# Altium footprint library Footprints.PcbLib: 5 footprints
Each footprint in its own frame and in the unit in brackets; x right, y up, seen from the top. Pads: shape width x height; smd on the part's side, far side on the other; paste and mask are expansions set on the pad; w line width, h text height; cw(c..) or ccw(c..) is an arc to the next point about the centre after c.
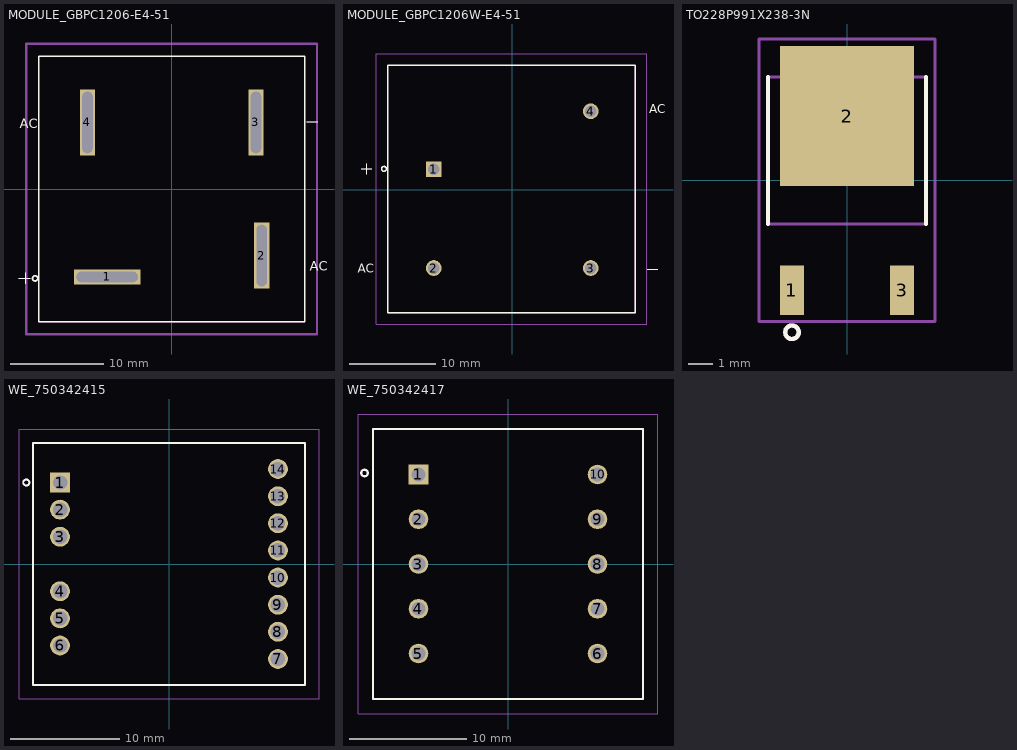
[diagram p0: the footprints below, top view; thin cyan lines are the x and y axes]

## MODULE_GBPC1206-E4-51 [mm]
height 7.87
pads (4):
  rect 7.104x1.614 hole 1.114 slot 6.604 at 0 deg mask+0: 1(-6.927,-9.45)
  rect 1.614x7.104 hole 1.114 slot 6.604 at 90 deg mask+0: 2(9.673,-7.15) 3(9.05,7.15) 4(-9.05,7.15)
Top Overlay:
  circle w0.178: c-14.679,-9.6 r0.279
  lines w0.127: -16.4,-9.6 -15.2,-9.6 ; -15.7,-10.2 -15.7,-9 ; 14.5,7.2 15.7,7.2
  lines w0.152: -14.275,-14.275 14.275,-14.275 14.275,14.275 -14.275,14.275 -14.275,-14.275
  text ".Designator" at -6,16 h1.02
  text "AC" at -16.3,6.5 h1.02
  text "AC" at 14.8,-8.8 h1.02
Mechanical 5:
  lines w0.127: -16.4,-9.6 -15.2,-9.6 ; -15.7,-10.2 -15.7,-9 ; 14.5,7.2 15.7,7.2 ; -14.275,-14.275 14.275,-14.275 14.275,14.275 -14.275,14.275 -14.275,-14.275
  text "PRELIMINARY" at -3,-3.8 h1.02
  text ".Designator" at -5,0 h1.02
Mechanical 15:
  lines w0.254: -15.609,-15.609 15.609,-15.609 15.609,15.609 -15.609,15.609 -15.609,-15.609
Drill Drawing:
  circle w0.178: c-14.679,-9.6 r0.279
Mechanical 17:
  text "LEAD LENGTH : 12.435MM" at -13.2,4.2 h1.27
3D body: height 7.87, standoff 0, extent -14.274,-14.274 14.274,14.274

## MODULE_GBPC1206W-E4-51 [mm]
height 7.87
pads (4):
  rect 1.824x1.824 hole 1.324 mask+0: 1(-9.05,2.35)
  round 1.824 hole 1.324 mask+0: 2(-9.05,-9.05) 3(9.05,-9.05) 4(9.05,9.05)
Top Overlay:
  circle w0.178: c-14.8,2.4 r0.279
  lines w0.127: -17.4,2.4 -16.2,2.4 ; -16.8,1.8 -16.8,3 ; 15.6,-9.2 16.8,-9.2
  lines w0.152: -14.35,-14.2 14.2,-14.2 14.2,14.35 -14.35,14.35 -14.35,-14.2
  text ".Designator" at -6,16 h1.02
  text "AC" at -17.8,-9.6 h1.02
  text "AC" at 15.8,8.8 h1.02
Mechanical 5:
  lines w0.127: -17.4,2.4 -16.2,2.4 ; -16.8,1.8 -16.8,3 ; 15.6,-9.2 16.8,-9.2 ; -14.35,-14.2 14.2,-14.2 14.2,14.35 -14.35,14.35 -14.35,-14.2
  text "PRELIMINARY" at -3,-3.8 h1.02
  text ".Designator" at -5,0 h1.02
Mechanical 15:
  lines w0.127: -15.684,-15.534 15.534,-15.534 15.534,15.684 -15.684,15.684 -15.684,-15.534
Drill Drawing:
  circle w0.178: c-14.8,2.4 r0.279
Mechanical 17:
  text "LEAD LENGTH : 23.93MM" at -13.2,4.2 h1.27
3D body: height 7.87, standoff 0, extent -14.349,-14.199 14.199,14.349

## TO228P991X238-3N [mm]
height 2.38
pads (3):
  rect 1x2.05 smd mask+0: 1(-2.285,-4.55) 3(2.285,-4.55)
  rect 5.55x5.8 smd mask+0: 2(0,2.65)
Top Overlay:
  circle w0.178: c-2.279,-6.3 r0.279
  lines w0.152: -3.27,-1.817 -3.27,4.277 ; 3.27,-1.817 3.27,4.277
  text ".Designator" at -5.5,6.6 h1.02
Mechanical 5:
  circle w0.178: c-2.279,-6.3 r0.279
  lines w0.127: -3.27,-1.817 3.27,-1.817 3.27,4.277 -3.27,4.277 -3.27,-1.817
  text ".Designator" at -5,-0.2 h1.02
  text "PRELIMINARY" at -2,-4.7 h1.02
Mechanical 15:
  lines w0.127: -3.65,-5.85 -3.65,5.85 3.65,5.85 3.65,-5.85 -3.65,-5.85
3D body: height 2.38, standoff 0, extent -3.269,-1.816 3.269,4.276

## WE_750342415 [mm] "TRANSFOERMER, TH"
height 16
pads (14):
  rect 1.82x1.82 / inner round 1.82 / far side rect 1.82x1.82 hole 1.32: 1(-10,7.48)
  round 1.82 hole 1.32: 2(-10,4.99) 3(-10,2.5) 4(-10,-2.5) 5(-10,-4.99) 6(-10,-7.48) 7(10,-8.715) 8(10,-6.225) 9(10,-3.735) 10(10,-1.245) 11(10,1.245) 12(10,3.735) 13(10,6.225) 14(10,8.715)
Top Overlay:
  circle w0.178: c-13.1,7.48 r0.279
  lines w0.178: -12.5,-11.1 12.5,-11.1 12.5,11.1 -12.5,11.1 -12.5,-11.1
  text ".Designator" at -1.524,12.954 h1.02
Bottom Overlay:
  lines w0.178: -12.5,-11.1 -12.5,-10.054 ; -12.5,-9.264 -12.5,-7.054 ; -12.5,-6.264 -12.5,-4.054 ; -12.5,-3.237 -12.5,-1.027 ; -12.5,-0.237 -12.5,1.973 ; -12.5,2.763 -12.5,4.973 ; -12.5,5.763 -12.5,7.973 ; -12.5,8.89 -12.5,11.1 -10.287,11.1 ; -10.894,-11.1 -8.627,-11.1 ; -9.5,11.1 -7.287,11.1 ; -7.894,-11.1 -5.627,-11.1 ; -6.5,11.1 -4.287,11.1 ; -4.894,-11.1 -2.627,-11.1 ; -3.5,11.1 -1.287,11.1 ; -1.894,-11.1 0.373,-11.1 ; -0.5,11.1 1.713,11.1 ; 1.106,-11.1 3.373,-11.1 ; 2.528,11.1 4.741,11.1 ; 4.106,-11.1 6.373,-11.1 ; 5.529,11.1 7.742,11.1 ; 7.106,-11.1 9.373,-11.1 ; 8.528,11.1 10.741,11.1 ; 10.233,-11.1 12.5,-11.1 12.5,-8.609 ; 12.5,-8.176 12.5,-5.685 ; 12.5,-5.176 12.5,-2.685 ; 12.5,-2.176 12.5,0.315 ; 12.5,0.824 12.5,3.315 ; 12.5,3.862 12.5,6.353 ; 12.5,6.862 12.5,9.353 ; 12.5,9.862 12.5,11.1
Mechanical 5:
  circle w0.127: c-13.1,7.48 r0.279
  lines w0.127: -12.5,-11.1 12.5,-11.1 12.5,11.1 -12.5,11.1 -12.5,-11.1
  text "PRELIMINARY" at -5.588,-7.112 h1.52
  text ".Designator" at -1.524,-0.508 h1.02
Mechanical 15:
  lines w0.05: -13.77,-12.37 -13.77,12.37 13.77,12.37 13.77,-12.37 -13.77,-12.37
Mechanical 17:
  text "LEAD LENGTH: 4:00 MM" at -10.668,9.652 h1
3D body: height 16, standoff 0, extent -12.5,-11.1 12.5,11.1

## WE_750342417 [mm] "TRANSFOERMER, TH"
height 17.53
pads (10):
  rect 1.67x1.67 / inner round 1.67 / far side rect 1.67x1.67 hole 1.17: 1(-7.62,7.62)
  round 1.67 hole 1.17: 2(-7.62,3.81) 3(-7.62,0) 4(-7.62,-3.81) 5(-7.62,-7.62) 6(7.62,-7.62) 7(7.62,-3.81) 8(7.62,0) 9(7.62,3.81) 10(7.62,7.62)
Top Layer:
  lines w0.178: 11.5,9 11.5,11.5
Top Overlay:
  circle w0.178: c-12.217,7.747 r0.279
  lines w0.178: -11.5,-11.5 -11.5,11.5 11.5,11.5 11.5,-11.5 -11.5,-11.5
  text ".Designator" at -1.524,12 h1.02
Bottom Overlay:
  lines w0.178: -11.5,-9.599 -11.5,-11.5 -9,-11.5 ; -11.5,-9.099 -11.5,-6.599 ; -11.5,-6.099 -11.5,-3.599 ; -11.5,-3.127 -11.5,-0.627 ; -11.5,-0.127 -11.5,2.373 ; -11.5,2.873 -11.5,5.373 ; -11.5,5.873 -11.5,8.373 ; -11.5,9 -11.5,11.5 -9,11.5 ; -8.5,-11.5 -6,-11.5 ; -8.5,11.5 -6,11.5 ; -5.5,-11.5 -3,-11.5 ; -5.5,11.5 -3,11.5 ; -2.5,-11.5 0,-11.5 ; -2.5,11.5 0,11.5 ; 0.5,-11.5 3,-11.5 ; 0.5,11.5 3,11.5 ; 3.5,-11.5 6,-11.5 ; 3.5,11.5 6,11.5 ; 6.5,-11.5 9,-11.5 ; 6.5,11.5 9,11.5 ; 9.5,-11.5 11.5,-11.5 11.5,-9.472 ; 9.5,11.5 11.5,11.5 11.5,9 ; 11.5,-8.972 11.5,-6.472 ; 11.5,-5.972 11.5,-3.472 ; 11.5,-3 11.5,-0.5 ; 11.5,0 11.5,2.5 ; 11.5,3 11.5,5.5 ; 11.5,6 11.5,8.5
Mechanical 5:
  circle w0.127: c-12.217,7.747 r0.279
  lines w0.127: -11.5,-11.5 -11.5,11.5 11.5,11.5 11.5,-11.5 -11.5,-11.5
  text ".Designator" at -1.524,-0.508 h1.02
  text "PRELIMINARY" at -3.81,-5.715 h1.52
Mechanical 15:
  lines w0.05: -12.77,-12.77 12.77,-12.77 12.77,12.77 -12.77,12.77 -12.77,-12.77
Mechanical 17:
  text "LEAD LENGTH: 4:00 MM" at -9.906,9.779 h1
3D body: height 17.53, standoff 0, extent -11.5,-11.5 11.5,11.5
